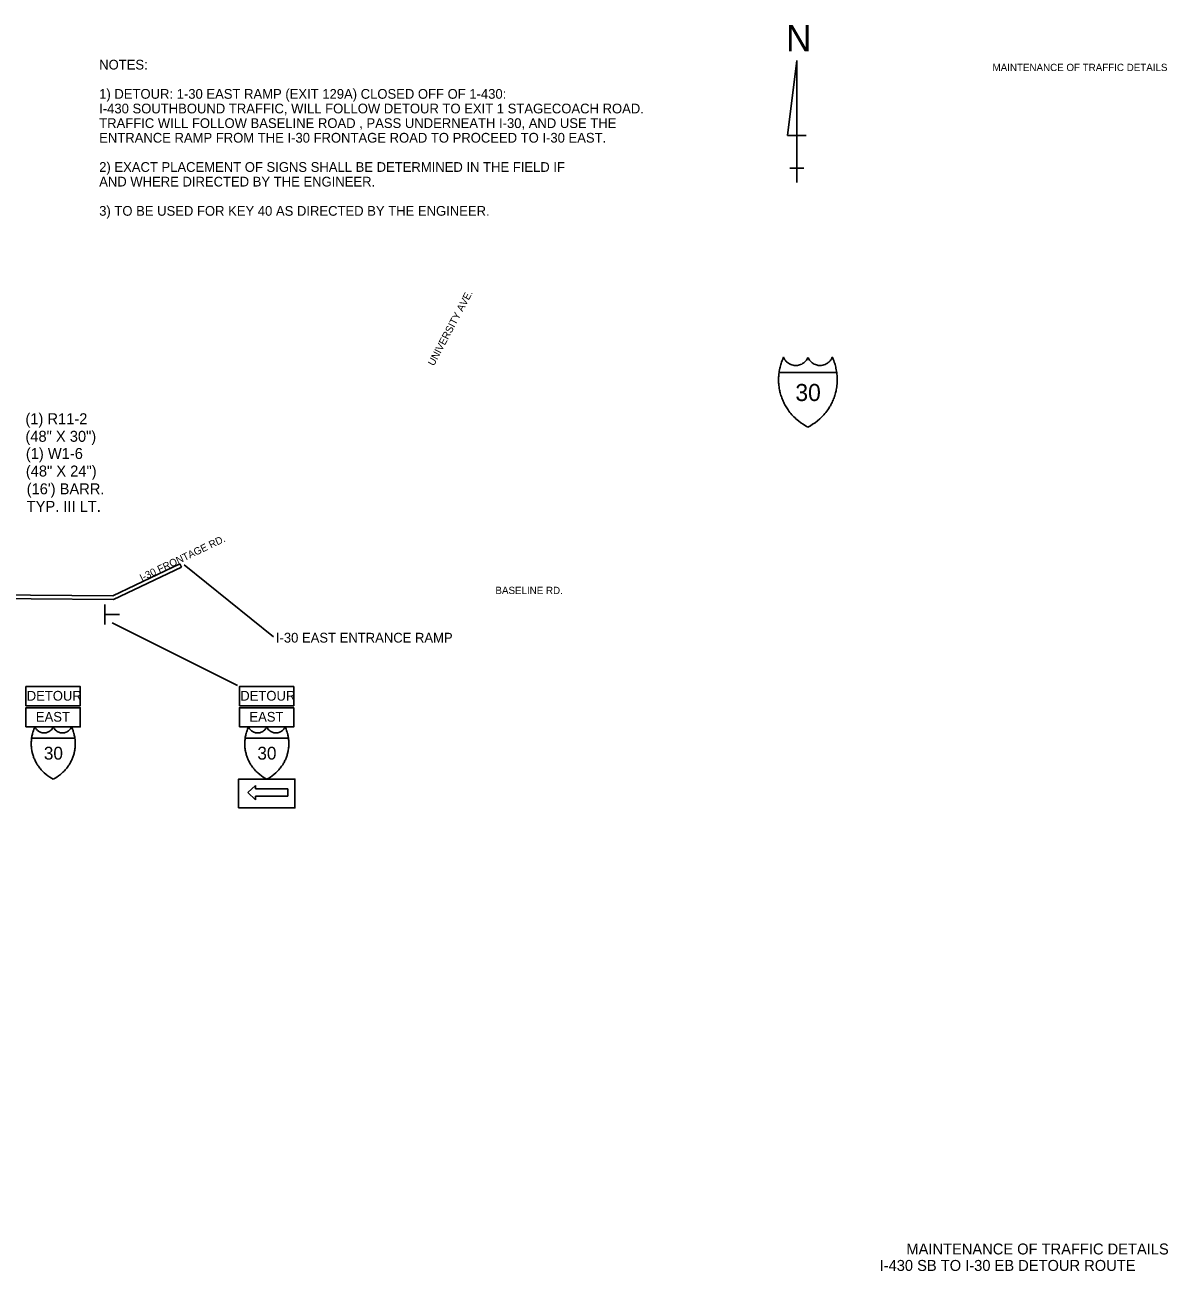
# Model space of a CAD drawing. Extents: x 637140 to 789215, y 877940 to 980201.
# Drawn here: x 695402 to 789215, y 877940 to 980201 of the extents above; entities that cross this region are included whole.
import ezdxf

# ---------------------------------------------------------------- set-up
doc = ezdxf.new("R2010")
doc.units = 0
for name, color, linetype in [('23', 7, 'Continuous'), ('DETOUR', 7, 'Continuous'), ('G-ANNO-TEXT', 7, 'Continuous'), ('Level 3', 7, 'Continuous'), ('Level 35', 7, 'Continuous'), ('Level 8', 7, 'Continuous'), ('R_Draft', 7, 'Continuous')]:
    doc.layers.add(name, color=color, linetype=linetype)

msp = doc.modelspace()

# ---------------------------------------------------------------- linework, layer by layer
at = {"layer": '23'}
for points in [[(757292, 951686), (757310, 951799), (757327, 951899), (757354, 952028), (757373, 952112), (757399, 952212), (757432, 952329), (757462, 952427), (757496, 952528), (757541, 952652), (757587, 952769), (757626, 952859), (757658, 952930), (757693, 952853), (757733, 952780), (757777, 952713), (757835, 952638), (757880, 952588), (757937, 952534), (757993, 952486), (758055, 952441), (758153, 952382), (758254, 952335), (758345, 952303), (758435, 952280), (758532, 952264), (758644, 952257), (758718, 952258), (758803, 952266), (758878, 952279), (758959, 952299), (759040, 952326), (759150, 952374), (759225, 952416), (759313, 952476), (759397, 952547), (759458, 952609), (759529, 952694), (759586, 952781), (759620, 952841), (759658, 952921)], [(759658, 952921), (759695, 952841), (759729, 952781), (759787, 952694), (759857, 952609), (759918, 952547), (760002, 952476), (760090, 952416), (760166, 952374), (760275, 952326), (760356, 952299), (760437, 952279), (760513, 952266), (760597, 952258), (760671, 952257), (760783, 952264), (760880, 952280), (760970, 952303), (761061, 952335), (761162, 952382), (761260, 952441), (761322, 952486), (761379, 952534), (761435, 952588), (761481, 952638), (761538, 952713), (761582, 952780), (761623, 952853), (761657, 952930), (761690, 952859), (761728, 952769), (761775, 952652), (761820, 952528), (761854, 952427), (761884, 952329), (761917, 952212), (761942, 952112), (761962, 952028), (761988, 951899), (762006, 951799), (762023, 951686)], [(759658, 947205), (759450, 947315), (759268, 947425), (759067, 947560), (758880, 947702), (758675, 947877), (758599, 947948), (758512, 948033), (758432, 948116), (758343, 948213), (758257, 948313), (758185, 948402), (758106, 948504), (758035, 948603), (757974, 948693), (757919, 948776), (757875, 948849), (757816, 948950), (757770, 949032), (757719, 949129), (757670, 949229), (757627, 949322), (757588, 949411), (757547, 949511), (757512, 949604), (757478, 949701), (757444, 949802), (757413, 949906), (757386, 950005), (757363, 950099), (757344, 950183), (757331, 950245), (757308, 950365), (757287, 950504), (757272, 950620), (757261, 950742), (757255, 950841), (757250, 950966), (757249, 951083), (757251, 951213), (757255, 951299), (757260, 951378), (757264, 951427), (757276, 951555), (757292, 951686)], [(762023, 951686), (757292, 951686)], [(757292, 951686), (762023, 951686)], [(762023, 951686), (762040, 951555), (762052, 951427), (762055, 951378), (762060, 951299), (762064, 951213), (762066, 951083), (762065, 950966), (762060, 950841), (762054, 950742), (762043, 950620), (762029, 950504), (762007, 950365), (761985, 950245), (761972, 950183), (761952, 950099), (761929, 950005), (761902, 949906), (761871, 949802), (761838, 949701), (761803, 949604), (761768, 949511), (761727, 949411), (761688, 949322), (761646, 949229), (761596, 949129), (761546, 949032), (761500, 948950), (761440, 948849), (761396, 948776), (761342, 948693), (761280, 948603), (761209, 948504), (761131, 948402), (761058, 948313), (760972, 948213), (760884, 948116), (760803, 948033), (760716, 947948), (760640, 947877), (760435, 947702), (760248, 947560), (760047, 947425), (759865, 947315), (759658, 947205)], [(695953, 921673), (695966, 921758), (695980, 921833), (696000, 921929), (696014, 921992), (696033, 922067), (696058, 922155), (696081, 922229), (696106, 922304), (696140, 922398), (696175, 922485), (696204, 922553), (696228, 922606), (696254, 922549), (696284, 922494), (696317, 922443), (696360, 922387), (696394, 922350), (696437, 922309), (696479, 922273), (696526, 922239), (696599, 922195), (696675, 922160), (696743, 922136), (696811, 922118), (696883, 922107), (696967, 922101), (697023, 922102), (697086, 922108), (697143, 922118), (697204, 922132), (697265, 922153), (697347, 922189), (697403, 922221), (697469, 922266), (697532, 922319), (697578, 922365), (697631, 922429), (697674, 922494), (697700, 922539), (697728, 922599)], [(697728, 922599), (697755, 922539), (697781, 922494), (697824, 922429), (697877, 922365), (697923, 922319), (697986, 922266), (698052, 922221), (698109, 922189), (698191, 922153), (698252, 922132), (698312, 922118), (698369, 922108), (698432, 922102), (698488, 922101), (698572, 922107), (698644, 922118), (698712, 922136), (698780, 922160), (698856, 922195), (698929, 922239), (698976, 922273), (699018, 922309), (699061, 922350), (699095, 922387), (699138, 922443), (699171, 922494), (699201, 922549), (699227, 922606), (699252, 922553), (699280, 922485), (699315, 922398), (699349, 922304), (699374, 922229), (699397, 922155), (699422, 922067), (699441, 921992), (699455, 921929), (699475, 921833), (699489, 921758), (699502, 921673)], [(713477, 921673), (713490, 921758), (713504, 921833), (713524, 921929), (713538, 921992), (713557, 922067), (713582, 922155), (713604, 922229), (713630, 922304), (713664, 922398), (713698, 922485), (713727, 922553), (713752, 922606), (713778, 922549), (713808, 922494), (713841, 922443), (713884, 922387), (713918, 922350), (713961, 922309), (714003, 922273), (714050, 922239), (714123, 922195), (714199, 922160), (714267, 922136), (714334, 922118), (714407, 922107), (714491, 922101), (714547, 922102), (714610, 922108), (714667, 922118), (714727, 922132), (714788, 922153), (714870, 922189), (714927, 922221), (714993, 922266), (715056, 922319), (715102, 922365), (715155, 922429), (715198, 922494), (715223, 922539), (715251, 922599)], [(715251, 922599), (715279, 922539), (715305, 922494), (715348, 922429), (715401, 922365), (715447, 922319), (715510, 922266), (715576, 922221), (715632, 922189), (715714, 922153), (715775, 922132), (715836, 922118), (715893, 922108), (715956, 922102), (716012, 922101), (716096, 922107), (716168, 922118), (716236, 922136), (716304, 922160), (716380, 922195), (716453, 922239), (716500, 922273), (716542, 922309), (716584, 922350), (716619, 922387), (716662, 922443), (716695, 922494), (716725, 922549), (716751, 922606), (716775, 922553), (716804, 922485), (716839, 922398), (716873, 922304), (716898, 922229), (716921, 922155), (716946, 922067), (716965, 921992), (716979, 921929), (716999, 921833), (717013, 921758), (717025, 921673)], [(697728, 918312), (697572, 918395), (697435, 918477), (697285, 918579), (697144, 918685), (696991, 918816), (696934, 918869), (696868, 918933), (696808, 918995), (696742, 919068), (696677, 919143), (696623, 919210), (696564, 919287), (696511, 919360), (696465, 919428), (696424, 919491), (696390, 919545), (696346, 919621), (696312, 919683), (696274, 919755), (696237, 919830), (696204, 919900), (696175, 919967), (696145, 920042), (696118, 920111), (696093, 920184), (696068, 920260), (696044, 920338), (696024, 920412), (696006, 920482), (695992, 920545), (695982, 920592), (695966, 920682), (695949, 920787), (695938, 920874), (695930, 920965), (695926, 921039), (695922, 921133), (695921, 921221), (695923, 921319), (695926, 921383), (695929, 921442), (695932, 921479), (695941, 921575), (695953, 921673)], [(699502, 921673), (695953, 921673)], [(695953, 921673), (699502, 921673)], [(699502, 921673), (699514, 921575), (699523, 921479), (699526, 921442), (699529, 921383), (699532, 921319), (699534, 921221), (699533, 921133), (699530, 921039), (699525, 920965), (699517, 920874), (699506, 920787), (699490, 920682), (699473, 920592), (699463, 920545), (699449, 920482), (699431, 920412), (699411, 920338), (699387, 920260), (699363, 920184), (699337, 920111), (699310, 920042), (699280, 919967), (699251, 919900), (699218, 919830), (699182, 919755), (699144, 919683), (699109, 919621), (699065, 919545), (699031, 919491), (698991, 919428), (698944, 919360), (698891, 919287), (698832, 919210), (698778, 919143), (698713, 919068), (698647, 918995), (698587, 918933), (698522, 918869), (698464, 918816), (698311, 918685), (698170, 918579), (698020, 918477), (697883, 918395), (697728, 918312)], [(715251, 918312), (715096, 918395), (714959, 918477), (714809, 918579), (714668, 918685), (714515, 918816), (714457, 918869), (714392, 918933), (714332, 918995), (714266, 919068), (714201, 919143), (714147, 919210), (714088, 919287), (714035, 919360), (713988, 919428), (713948, 919491), (713914, 919545), (713870, 919621), (713835, 919683), (713797, 919755), (713760, 919830), (713728, 919900), (713699, 919967), (713668, 920042), (713642, 920111), (713616, 920184), (713591, 920260), (713568, 920338), (713548, 920412), (713530, 920482), (713516, 920545), (713506, 920592), (713489, 920682), (713473, 920787), (713462, 920874), (713454, 920965), (713449, 921039), (713446, 921133), (713445, 921221), (713447, 921319), (713449, 921383), (713453, 921442), (713456, 921479), (713465, 921575), (713477, 921673)], [(717025, 921673), (713477, 921673)], [(713477, 921673), (717025, 921673)], [(717025, 921673), (717038, 921575), (717047, 921479), (717050, 921442), (717053, 921383), (717056, 921319), (717058, 921221), (717057, 921133), (717053, 921039), (717049, 920965), (717041, 920874), (717030, 920787), (717013, 920682), (716997, 920592), (716987, 920545), (716973, 920482), (716955, 920412), (716935, 920338), (716911, 920260), (716886, 920184), (716861, 920111), (716834, 920042), (716804, 919967), (716774, 919900), (716742, 919830), (716705, 919755), (716667, 919683), (716633, 919621), (716588, 919545), (716555, 919491), (716514, 919428), (716468, 919360), (716415, 919287), (716356, 919210), (716302, 919143), (716237, 919068), (716171, 918995), (716111, 918933), (716045, 918869), (715988, 918816), (715835, 918685), (715694, 918579), (715544, 918477), (715407, 918395), (715251, 918312)]]:
    msp.add_lwpolyline(points, dxfattribs=at)
at = {"layer": 'DETOUR'}
for p, q in [((708122, 935971), (708250, 935703)), ((701973, 932651), (701973, 930988)), ((701973, 931820), (703170, 931820))]:
    msp.add_line(p, q, dxfattribs=at)
for points in [[(708250, 935703), (702682, 933044), (668872, 933321), (667017, 933334), (661042, 933421), (659316, 933504), (661624, 937474), (662654, 938240), (667020, 939948), (667794, 940423), (669136, 941654), (670463, 943124), (670991, 945324), (673490, 968061)], [(673786, 968028), (671284, 945273), (670734, 942981), (669347, 941444), (667974, 940185), (667153, 939681), (662799, 937978), (661850, 937272), (659819, 933777), (661051, 933718), (667020, 933631), (668874, 933618), (702615, 933342), (708122, 935971)]]:
    msp.add_lwpolyline(points, dxfattribs=at)
at = {"layer": 'Level 3'}
msp.add_line((716971, 917502), (716971, 916916), dxfattribs=at)
at = {"layer": 'Level 8'}
for p, q in [((713695, 917209), (714338, 917795)), ((714338, 917502), (714338, 917795)), ((716971, 917502), (714338, 917502)), ((714338, 916622), (713695, 917209)), ((716971, 916916), (714338, 916916)), ((714338, 916622), (714338, 916916))]:
    msp.add_line(p, q, dxfattribs=at)
for points in [[(695484, 924326), (699939, 924326), (699939, 925900), (695484, 925900)], [(713008, 924326), (717463, 924326), (717463, 925900), (713008, 925900)], [(695484, 922599), (699939, 922599), (699939, 924173), (695484, 924173)], [(713008, 922599), (717463, 922599), (717463, 924173), (713008, 924173)], [(712943, 915951), (717560, 915951), (717560, 918312), (712943, 918312)]]:
    msp.add_lwpolyline(points, close=True, dxfattribs=at)
at = {"layer": 'R_Draft'}
for p, q in [((758747, 977291), (757977, 971132)), ((758747, 967282), (758747, 977291)), ((757977, 971132), (759517, 971132)), ((758166, 968452), (759321, 968452)), ((715807, 929993), (708480, 935902)), ((702566, 931148), (712858, 925999))]:
    msp.add_line(p, q, dxfattribs=at)

# ---------------------------------------------------------------- texts
at = {"layer": 'G-ANNO-TEXT'}
for s, height, p in [('MAINTENANCE OF TRAFFIC DETAILS', 600, (774810, 976414)), ('30', 1402.1, (758630, 949337)), ('30', 1051.6, (696957, 919912)), ('30', 1051.6, (714480, 919912)), ('MAINTENANCE OF TRAFFIC DETAILS', 900, (767739, 879303)), ('I-430 SB TO I-30 EB DETOUR ROUTE', 900, (765543, 877953))]:
    msp.add_text(s, height=height, dxfattribs=at).set_placement(p)
at = {"layer": 'Level 35'}
for s, rotation, p in [('UNIVERSITY AVE.', 62.09095, (728960, 952172)), ('I-30 FRONTAGE RD.', 25.52412, (704997, 934526))]:
    msp.add_text(s, height=600, rotation=rotation, dxfattribs=at).set_placement(p)
msp.add_text('BASELINE RD.', height=600, dxfattribs=at).set_placement((734016, 933499))
at = {"layer": 'Level 8'}
for s, height, p in [('(1) R11-2', 900.3, (695444, 947433)), ('(48" X 30")', 900.31, (695444, 945992)), ('(1) W1-6', 900.3, (695478, 944583)), ('(48" X 24")', 900.31, (695478, 943143)), ("(16') BARR.", 900.31, (695546, 941683)), ('TYP. III LT.', 900.31, (695546, 940242))]:
    msp.add_text(s, height=height, dxfattribs=at).set_placement(p)
at = {"layer": 'R_Draft'}
for s, height, p in [('N', 2160, (757857, 978041)), ('NOTES:', 800, (701497, 976541)), ('1) DETOUR: 1-30 EAST RAMP (EXIT 129A) CLOSED OFF OF 1-430:', 800, (701497, 974141)), ('I-430 SOUTHBOUND TRAFFIC, WILL FOLLOW DETOUR TO EXIT 1 STAGECOACH ROAD.', 800, (701497, 972941)), ('TRAFFIC WILL FOLLOW BASELINE ROAD , PASS UNDERNEATH I-30, AND USE THE', 800, (701497, 971741)), ('ENTRANCE RAMP FROM THE I-30 FRONTAGE ROAD TO PROCEED TO I-30 EAST.', 800, (701497, 970541)), ('2) EXACT PLACEMENT OF SIGNS SHALL BE DETERMINED IN THE FIELD IF ', 800, (701497, 968141)), ('AND WHERE DIRECTED BY THE ENGINEER.', 800, (701497, 966941)), ('3) TO BE USED FOR KEY 40 AS DIRECTED BY THE ENGINEER.', 800, (701497, 964541)), ('I-30 EAST ENTRANCE RAMP', 800, (715999, 929516)), ('DETOUR', 800, (695552, 924751)), ('DETOUR', 800, (713076, 924751)), ('EAST', 800, (696301, 923024)), ('EAST', 800, (713825, 923024))]:
    msp.add_text(s, height=height, dxfattribs=at).set_placement(p)

doc.saveas('drawing.dxf')
